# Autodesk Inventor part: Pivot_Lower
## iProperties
Shininess: 0.0
Length Units: 11272
Angle Units: 11279
Time Units: 11290
Mass Units: 11283
Length Display Precision: 2
Angle Display Precision: 1
Created: 1999-05
Part Number: Pivot_Lower
Document SubType Name: Modeling
Designer: Administrator
Density: 1 g/cm^3
Density: 0.0
Volumn: 0.0
Area: 0.0
PropertySet Name: Model Information
Control State: 0
Master: False
Checked Out: False
Author: Administrator
